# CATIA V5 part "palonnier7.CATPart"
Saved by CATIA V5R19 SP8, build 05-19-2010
Part number: palonnier7
Bounding box of the stored display mesh (mm): x -135 to -107, y 19.529 to 51.473, z -52.571 to -24.739
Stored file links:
  G:\EU_thinkMotion\CFAO_2010\MMS_groupe2\MMS_groupe2\A reprendre\jcauchy\palonnier7.CATPart
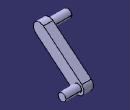
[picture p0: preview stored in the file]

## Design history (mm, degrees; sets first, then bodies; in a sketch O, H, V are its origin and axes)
Parameters
  Rayonfixation_palonnier7 = 2.5 mm
  Largeurpalonnier_palonnier7 = 8 mm
  Hauteurpalonnier_palonnier7 = 6 mm
  Longueurpalonnier = 31.3 mm
Set1
  Plane1: stored without definition
  Sketch1 on Plane1, origin (-120, 0, 0), H (0, -1, 0), V (0, 0, 1)
    line L1 (-50.1391, -45.4847) -> (-25.9349, -25.6391)
    point P1 (-50.1391, -45.4847)
    point P2 (-25.9349, -25.6391)
    arc A1 centre (-23.3987, -28.7323) radius 4 from (-20.8625, -31.8255) to (-25.9349, -25.6391) ccw
    point P3 (-23.3987, -28.7323)
    point P4 (-25.9349, -25.6391)
    point P5 (-20.8625, -31.8255)
    line L2 (-20.8625, -31.8255) -> (-45.0667, -51.6711)
    point P6 (-20.8625, -31.8255)
    point P7 (-45.0667, -51.6711)
    arc A2 centre (-47.6029, -48.5779) radius 4 from (-50.1391, -45.4847) to (-45.0667, -51.6711) ccw
    point P8 (-47.6029, -48.5779)
    point P9 (-50.1391, -45.4847)
    point P10 (-45.0667, -51.6711)
    distance L2 L1 = 8 {= Largeurpalonnier_palonnier7}
    distance P8 P3 = 31.3 {= Longueurpalonnier}
    tangency: A1 L1, L2 A1, A2 L1, A2 L2
    coincidence: P4 P2, P5 P6, P1 P9, P10 P7
  Point1: stored without definition
  DatumPoint1
  DatumPoint2
  Plane2: stored without definition
  Point2: stored without definition
Body1 (main body)
  Pad1: profile Sketch1, direction (-1, 0, 0), length 3 {= Hauteurpalonnier_palonnier7 /2}, mirrored extent
  Sketch2 on start face of Pad1, origin (-117, 0, 0), H (0, 1, 0), V (0, 0, 1)
    circle A1 centre (47.6029, -48.5779) radius 2.5
    point P1 (47.6029, -48.5779)
    reference projected arc E1 centre (47.6029, -48.5779) radius 4 from (45.0667, -51.6711) to (50.1391, -45.4847) ccw from edge [start face of Pad1 | face of Pad1 from Sketch1.A2]
    radius A1 = 2.5 {= Rayonfixation_palonnier7}
    distance P1 E1 = 4 {= Largeurpalonnier_palonnier7 /2}
  Pad2: profile Sketch2, direction (1, 0, 0), length 10
  Sketch3 on Plane2, origin (-120, 0, 0), H (0, -1, 0), V (0, 0, 1)
    circle A1 centre (-23.3987, -28.7323) radius 2.5
    point P1 (-23.3987, -28.7323)
    reference projected arc E1 centre (-23.3987, -28.7323) radius 4 from (-20.8625, -31.8255) to (-25.9349, -25.6391) ccw from edge [face of Pad1 from Sketch1.A1 | end face of Pad1]
    radius A1 = 2.5 {= Rayonfixation_palonnier7}
    distance P1 E1 = 4 {= Largeurpalonnier_palonnier7 /2}
  Pad3: profile Sketch3, direction (-1, 0, 0), length 15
